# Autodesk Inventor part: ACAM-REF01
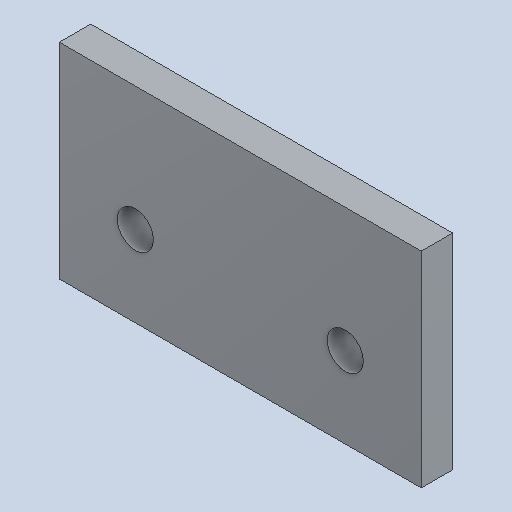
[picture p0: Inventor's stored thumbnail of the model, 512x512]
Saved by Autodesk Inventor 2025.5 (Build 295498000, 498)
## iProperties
Created: 2026-10
Part Number: ACAM-REF01
Material: Genérico
Document SubType Name: Modeling
Designer: Luis M
Density: 1 g/cm^3
Appearance: Valor por defecto
Description: Base Jaco2 — referencia
Material_BOM: Referencia
Proceso_BOM: Referencia
Author: Luis M
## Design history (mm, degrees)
feature "Base1"
node "Sólido1"
